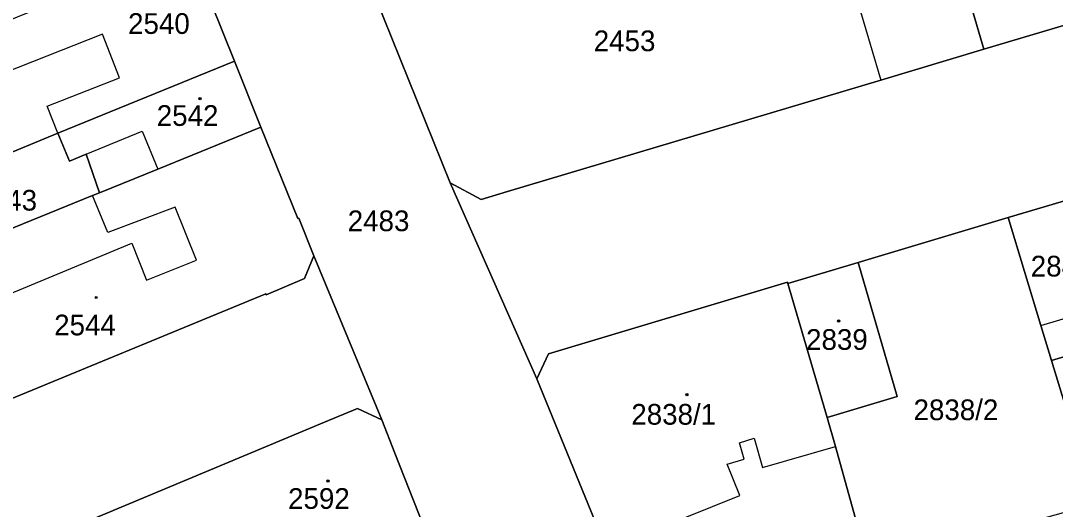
# Model space of a CAD drawing. Extents: x -596233 to -595156, y -1161235 to -1159375.
# Drawn here: x -595702.6 to -595617.7, y -1160659.5 to -1160619.4 of the extents above; entities that cross this region are included whole.
import ezdxf

# ---------------------------------------------------------------- set-up
doc = ezdxf.new("R2010")
doc.units = 0
for name, color, linetype in [('KN_CAR_KR', 7, 'Continuous'), ('KN_KULTURY', 7, 'Continuous'), ('KN_PARC_CIS_POZ', 7, 'Continuous'), ('KN_PARC_CIS_STAV', 7, 'Continuous'), ('KN_PARC_PLOCHA', 7, 'Continuous'), ('parcely_l', 7, 'Continuous')]:
    doc.layers.add(name, color=color, linetype=linetype)

msp = doc.modelspace()

# ---------------------------------------------------------------- linework, layer by layer
at = {"layer": 'KN_CAR_KR'}
for points in [[(-595635.39, -1160612.99), (-595632.05, -1160624.29)], [(-595695.86, -1160620.52), (-595707.37, -1160625.04)], [(-595694.46, -1160624.09), (-595695.86, -1160620.52)], [(-595700.39, -1160626.42), (-595694.46, -1160624.09)], [(-595699.52, -1160628.65), (-595700.39, -1160626.42)], [(-595697.19, -1160630.37), (-595692.62, -1160628.47)], [(-595692.62, -1160628.47), (-595691.34, -1160631.58)], [(-595695.44, -1160636.79), (-595696.69, -1160633.76)], [(-595689.91, -1160634.71), (-595695.44, -1160636.79)], [(-595688.16, -1160639.06), (-595689.91, -1160634.71)], [(-595708.81, -1160644.05), (-595693.47, -1160637.66)], [(-595693.47, -1160637.66), (-595692.26, -1160640.7)], [(-595692.26, -1160640.7), (-595688.16, -1160639.06)], [(-595618.92, -1160644.43), (-595612.23, -1160642.43)], [(-595643.63, -1160654.06), (-595642.44, -1160653.68)], [(-595643.25, -1160655.39), (-595643.63, -1160654.06)], [(-595642.44, -1160653.68), (-595641.74, -1160656.07)], [(-595641.74, -1160656.07), (-595635.77, -1160654.35)], [(-595644.64, -1160655.79), (-595643.25, -1160655.39)], [(-595643.61, -1160658.38), (-595644.64, -1160655.79)], [(-595654.55, -1160662.79), (-595643.61, -1160658.38)]]:
    msp.add_lwpolyline(points, dxfattribs=at)
at = {"layer": 'KN_KULTURY'}
for centre, radius in [((-595687.87, -1160625.81), 0.09), ((-595687.87, -1160625.81), 0.0398), ((-595696.38, -1160642.12), 0.09), ((-595696.38, -1160642.12), 0.0398), ((-595635.51, -1160644.05), 0.09), ((-595635.51, -1160644.05), 0.0398), ((-595647.95, -1160650.09), 0.09), ((-595647.95, -1160650.09), 0.0398), ((-595677.37, -1160657.18), 0.09), ((-595677.37, -1160657.18), 0.0398)]:
    msp.add_circle(centre, radius, dxfattribs=at)
at = {"layer": 'KN_PARC_PLOCHA'}
for points in [[(-595626.92, -1160610.44), (-595623.6, -1160621.75), (-595632.05, -1160624.29), (-595662.65, -1160633.42), (-595664.83, -1160634.09), (-595667.35, -1160632.72), (-595675.55, -1160612.32), (-595675.45, -1160612.28), (-595664.11, -1160608.68), (-595661.87, -1160607.97), (-595660.04, -1160607.39), (-595648.86, -1160603.84), (-595642.4, -1160601.79), (-595640.76, -1160601.27), (-595639.95, -1160603.83), (-595644.29, -1160605.21), (-595643.1, -1160608.87), (-595637.13, -1160607.12), (-595635.39, -1160612.99)], [(-595615.68, -1160619.23), (-595615.82, -1160619.27), (-595615.78, -1160619.42), (-595623.6, -1160621.75), (-595626.92, -1160610.44), (-595626.96, -1160610.31), (-595628.11, -1160606.38), (-595620.14, -1160604.22), (-595619.01, -1160608)], [(-595685.05, -1160622.72), (-595699.52, -1160628.65), (-595704.82, -1160630.82), (-595707.37, -1160625.04), (-595708.75, -1160621.53), (-595703.31, -1160619.29), (-595702.83, -1160619.09), (-595697.24, -1160616.79), (-595688.8, -1160613.32)], [(-595682.89, -1160628.14), (-595691.34, -1160631.58), (-595696.11, -1160633.52), (-595697.19, -1160630.37), (-595698.57, -1160630.94), (-595699.52, -1160628.65), (-595685.05, -1160622.72)], [(-595696.11, -1160633.52), (-595696.69, -1160633.76), (-595708.12, -1160638.41), (-595710.31, -1160633.07), (-595709.1, -1160632.57), (-595705.72, -1160631.19), (-595704.82, -1160630.82), (-595699.52, -1160628.65), (-595698.57, -1160630.94), (-595697.19, -1160630.37)], [(-595678.53, -1160638.71), (-595679.29, -1160640.57), (-595682.45, -1160641.9), (-595682.48, -1160641.83), (-595705.69, -1160651.41), (-595708.22, -1160645.45), (-595708.81, -1160644.05), (-595709.52, -1160642.37), (-595708.18, -1160641.71), (-595707.27, -1160640.35), (-595708.12, -1160638.41), (-595696.69, -1160633.76), (-595696.11, -1160633.52), (-595691.34, -1160631.58), (-595682.89, -1160628.14), (-595679.85, -1160635.65), (-595679.77, -1160635.62)], [(-595611.37, -1160645.31), (-595618.05, -1160647.3), (-595618.92, -1160644.43), (-595621.6, -1160635.57), (-595614.86, -1160633.56), (-595612.23, -1160642.43)], [(-595618.05, -1160647.3), (-595614.45, -1160659.13), (-595616.11, -1160659.52), (-595633.01, -1160664.23), (-595633.9, -1160661.05), (-595635.77, -1160654.35), (-595636.46, -1160651.97), (-595630.7, -1160650.24), (-595633.91, -1160639.25), (-595621.6, -1160635.57), (-595618.92, -1160644.43)], [(-595636.46, -1160651.97), (-595639.67, -1160640.98), (-595633.91, -1160639.25), (-595630.7, -1160650.24)], [(-595639.67, -1160640.98), (-595636.46, -1160651.97), (-595635.77, -1160654.35), (-595633.9, -1160661.05), (-595633.01, -1160664.23), (-595639.85, -1160666.14), (-595643.27, -1160667.09), (-595651.49, -1160670.21), (-595652.89, -1160666.82), (-595654.55, -1160662.79), (-595660.25, -1160648.81), (-595659.29, -1160646.75), (-595639.71, -1160640.86)], [(-595607.81, -1160657.27), (-595614.45, -1160659.13), (-595618.05, -1160647.3), (-595611.37, -1160645.31)], [(-595672.95, -1160652.16), (-595671.89, -1160654.89), (-595669.54, -1160660.85), (-595678.32, -1160664.43), (-595680.92, -1160665.54), (-595688.87, -1160668.73), (-595694.19, -1160670.91), (-595696.04, -1160671.68), (-595699.97, -1160661.68), (-595695.83, -1160659.95), (-595690.66, -1160657.81), (-595677.65, -1160652.36), (-595674.97, -1160651.22)]]:
    msp.add_lwpolyline(points, close=True, dxfattribs=at)
for points in [[(-595675.55, -1160612.32), (-595667.35, -1160632.72), (-595660.25, -1160648.81), (-595654.55, -1160662.79), (-595652.89, -1160666.82), (-595651.49, -1160670.21), (-595647.86, -1160679.17), (-595645.62, -1160684.7), (-595645.55, -1160684.68), (-595645.52, -1160684.78), (-595645.64, -1160684.82), (-595641.92, -1160694.35), (-595638.54, -1160702.86), (-595635.78, -1160709.8), (-595633.56, -1160717.67), (-595631.88, -1160723.47), (-595630.26, -1160729.1), (-595630.06, -1160729.06), (-595630.02, -1160729.25), (-595630.2, -1160729.28), (-595627.8, -1160737.78)], [(-595669.54, -1160660.85), (-595671.89, -1160654.89), (-595672.95, -1160652.16), (-595678.53, -1160638.71), (-595679.77, -1160635.62), (-595679.85, -1160635.65), (-595682.89, -1160628.14), (-595685.05, -1160622.72), (-595688.8, -1160613.32)], [(-595614.86, -1160633.56), (-595621.6, -1160635.57), (-595633.91, -1160639.25), (-595639.67, -1160640.98), (-595639.71, -1160640.86), (-595659.29, -1160646.75), (-595660.25, -1160648.81), (-595667.35, -1160632.72), (-595664.83, -1160634.09), (-595662.65, -1160633.42), (-595632.05, -1160624.29), (-595623.6, -1160621.75), (-595615.78, -1160619.42)], [(-595705.69, -1160651.41), (-595682.48, -1160641.83), (-595682.45, -1160641.9), (-595679.29, -1160640.57), (-595678.53, -1160638.71), (-595672.95, -1160652.16), (-595674.97, -1160651.22), (-595677.65, -1160652.36), (-595690.66, -1160657.81), (-595695.83, -1160659.95), (-595699.97, -1160661.68), (-595709.22, -1160665.55)]]:
    msp.add_lwpolyline(points, dxfattribs=at)
at = {"layer": 'parcely_l'}
for points in [[(-595626.92, -1160610.44), (-595623.6, -1160621.75)], [(-595667.35, -1160632.72), (-595675.55, -1160612.32), (-595675.45, -1160612.28)], [(-595685.05, -1160622.72), (-595688.8, -1160613.32)], [(-595623.6, -1160621.75), (-595615.78, -1160619.42), (-595615.82, -1160619.27), (-595615.68, -1160619.23)], [(-595623.6, -1160621.75), (-595632.05, -1160624.29), (-595662.65, -1160633.42), (-595664.83, -1160634.09), (-595667.35, -1160632.72)], [(-595685.05, -1160622.72), (-595699.52, -1160628.65)], [(-595682.89, -1160628.14), (-595685.05, -1160622.72)], [(-595704.82, -1160630.82), (-595699.52, -1160628.65)], [(-595699.52, -1160628.65), (-595698.57, -1160630.94), (-595697.19, -1160630.37), (-595696.11, -1160633.52)], [(-595696.11, -1160633.52), (-595691.34, -1160631.58), (-595682.89, -1160628.14)], [(-595682.89, -1160628.14), (-595679.85, -1160635.65), (-595679.77, -1160635.62), (-595678.53, -1160638.71)], [(-595667.35, -1160632.72), (-595660.25, -1160648.81)], [(-595708.12, -1160638.41), (-595696.69, -1160633.76), (-595696.11, -1160633.52)], [(-595621.6, -1160635.57), (-595614.86, -1160633.56)], [(-595633.91, -1160639.25), (-595621.6, -1160635.57)], [(-595621.6, -1160635.57), (-595618.92, -1160644.43), (-595618.05, -1160647.3)], [(-595705.69, -1160651.41), (-595682.48, -1160641.83), (-595682.45, -1160641.9), (-595679.29, -1160640.57), (-595678.53, -1160638.71)], [(-595678.53, -1160638.71), (-595672.95, -1160652.16)], [(-595639.67, -1160640.98), (-595633.91, -1160639.25)], [(-595636.46, -1160651.97), (-595630.7, -1160650.24), (-595633.91, -1160639.25)], [(-595660.25, -1160648.81), (-595659.29, -1160646.75), (-595639.71, -1160640.86), (-595639.67, -1160640.98)], [(-595639.67, -1160640.98), (-595636.46, -1160651.97)], [(-595618.05, -1160647.3), (-595611.37, -1160645.31)], [(-595614.45, -1160659.13), (-595618.05, -1160647.3)], [(-595651.49, -1160670.21), (-595652.89, -1160666.82), (-595654.55, -1160662.79), (-595660.25, -1160648.81)], [(-595672.95, -1160652.16), (-595674.97, -1160651.22), (-595677.65, -1160652.36), (-595690.66, -1160657.81), (-595695.83, -1160659.95), (-595699.97, -1160661.68)], [(-595672.95, -1160652.16), (-595671.89, -1160654.89), (-595669.54, -1160660.85)], [(-595636.46, -1160651.97), (-595635.77, -1160654.35), (-595633.9, -1160661.05), (-595633.01, -1160664.23)]]:
    msp.add_lwpolyline(points, dxfattribs=at)

# ---------------------------------------------------------------- texts
at = {"layer": 'KN_PARC_CIS_POZ'}
for s, p in [('2543', (-595706.2866, -1160634.99)), ('2483', (-595675.7566, -1160636.68)), ('2838/2', (-595629.3666, -1160652.19))]:
    msp.add_text(s, height=1.7, dxfattribs=at).set_placement(p)
at = {"layer": 'KN_PARC_CIS_STAV'}
for s, p in [('2540', (-595693.7666, -1160620.49)), ('2453', (-595655.5866, -1160621.91)), ('2542', (-595691.4166, -1160628.04)), ('2840', (-595619.7566, -1160640.4)), ('2544', (-595699.8266, -1160645.23)), ('2839', (-595638.1766, -1160646.42)), ('2838/1', (-595652.5066, -1160652.56)), ('2592', (-595680.6466, -1160659.47))]:
    msp.add_text(s, height=1.7, dxfattribs=at).set_placement(p)

doc.saveas('drawing.dxf')
